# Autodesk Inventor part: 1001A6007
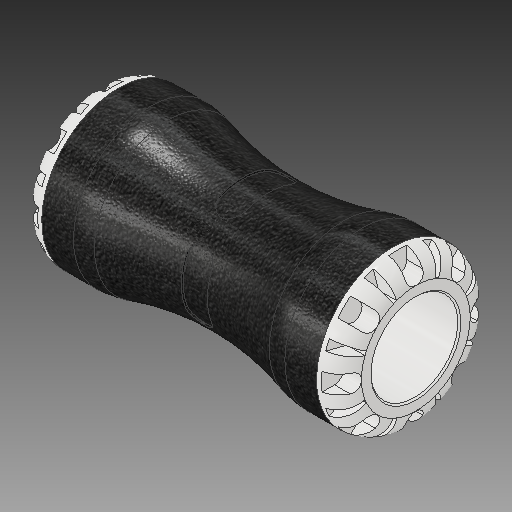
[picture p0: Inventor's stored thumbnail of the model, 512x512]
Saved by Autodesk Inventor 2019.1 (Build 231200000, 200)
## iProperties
Created: 2016-12
Part Number: 1001A6007
Material: PVC-Piping
Description: PLASSON COUPLER 3/4''IPS x 3/4''IPS SERIES 1
Document SubType Name: Modeling
Designer: KIM
Mass: 95.2094 g
Surface Area: 200.83 cm^2
Volume: 68.0067 cm^3
Density: 1.4 g/cm^3
Appearance: White
ILogicFactory: False
Author: KIM
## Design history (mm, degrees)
derived "1001A.ipt"
feature "Solid1::1001A.ipt"
tag "TaggingFeature1"
body "Solid1"
other parameters: "d2" = 48.006, "d4" = 2.21667, "d11" = 5.496, "d13" = 5.496, "d14" = 0, "d16" = 360 deg, "d18" = 8 deg, "d19" = 0.532, "d20" = 8 deg, "d21" = 0.532, "d23" = 0, "d25" = 360 deg, "d27" = 18.796, "d28" = 6.65, "d29" = 7.98, "d30" = 7.98, "d31" = 0, "d33" = 0, "d37" = 19.558, "d38" = 0.4699, "d43" = 3.325, "d44" = 26.6, "d45" = 19.558, "d46" = 37.592, "d47" = 46.99, "d48" = 97.79, "d50" = 360 deg, "d54" = 0.5, "d_" = 26.6, "E_" = 46.99, "H_" = 97.79, "l_" = 48.006, "d12" = 33.25, "d42" = 46.99, "d52" = 6.87
